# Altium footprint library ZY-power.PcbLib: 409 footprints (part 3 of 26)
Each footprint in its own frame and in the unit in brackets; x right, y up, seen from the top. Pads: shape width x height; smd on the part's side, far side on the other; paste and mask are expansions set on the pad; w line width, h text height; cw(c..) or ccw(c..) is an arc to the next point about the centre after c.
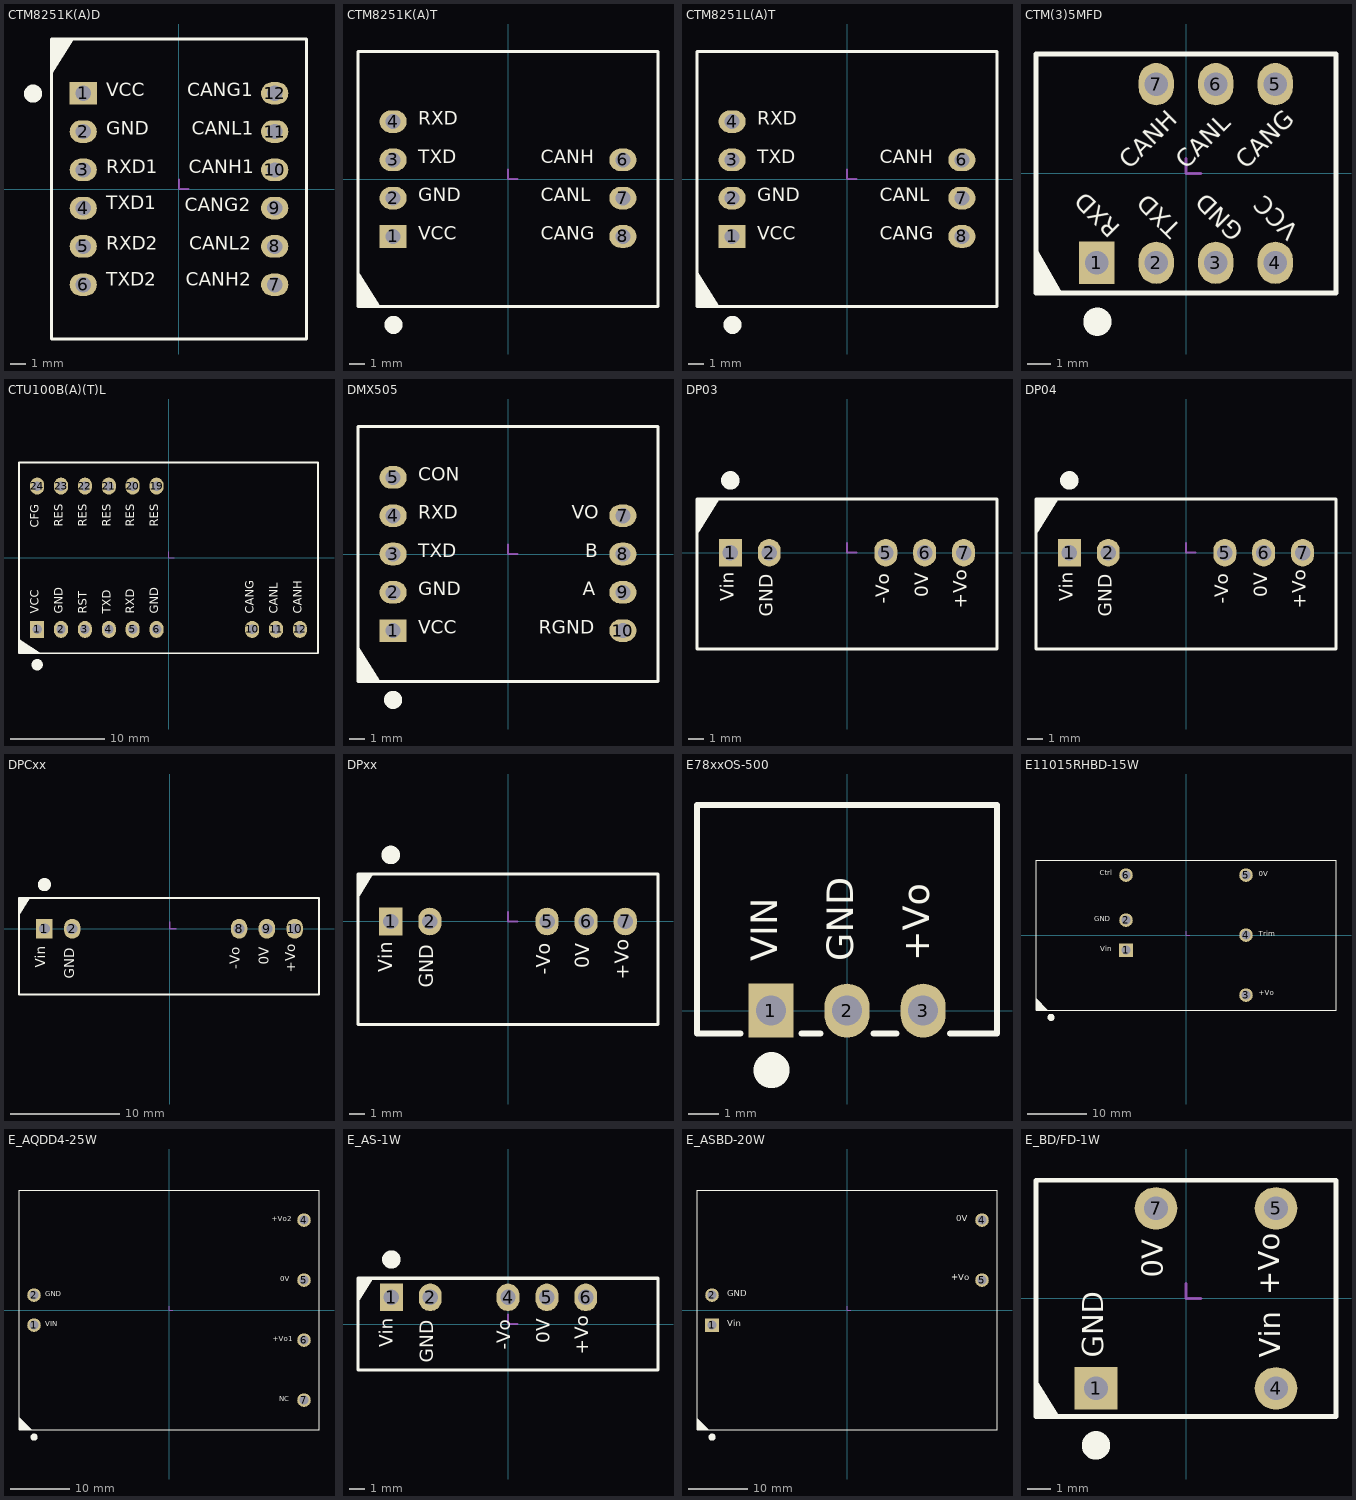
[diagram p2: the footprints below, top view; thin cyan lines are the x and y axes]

## CTM8251K(A)D [mm]
height 7.1
pads (12):
  rect 1.8x1.5 hole 1: 1(-6.35,6.35)
  oval 1.8x1.5 hole 1: 2(-6.35,3.81) 3(-6.35,1.27) 4(-6.35,-1.27) 5(-6.35,-3.81) 6(-6.35,-6.35) 7(6.35,-6.35) 8(6.35,-3.81) 9(6.35,-1.27) 10(6.35,1.27) 11(6.35,3.81) 12(6.35,6.35)
Top Overlay:
  circle w1: c-9.675,6.323 r0.1
  region: -8.45,7.62 -8.45,9.95 -6.99,9.95
  lines w0.2: -8.45,-9.95 -8.45,9.95 8.45,9.95 8.45,-9.95 -8.45,-9.95
  text "RXD2" at -4.827,-4.318 h1.52
  text "TXD2" at -4.827,-6.731 h1.52
  text "CANH2" at 0.457,-6.731 h1.52
  text "CANL2" at 0.683,-4.318 h1.52
  text "TXD1" at -4.827,-1.651 h1.52
  text "RXD1" at -4.827,0.762 h1.52
  text "GND" at -4.827,3.302 h1.52
  text "VCC" at -4.826,5.842 h1.52
  text "CANL1" at 0.861,3.302 h1.52
  text "CANH1" at 0.635,0.762 h1.52
  text "CANG2" at 0.381,-1.778 h1.52
  text "CANG1" at 0.559,5.842 h1.52
Mechanical 15:
  lines w0.127: 0,0.635 0,0 0.635,0
3D body "zhen01.stp": height 6.09, standoff -4.41, extent 6.1,6.1 6.6,6.6
3D body "zhen01.stp": height 6.09, standoff -4.41, extent 6.1,3.56 6.6,4.06
3D body "zhen01.stp": height 6.09, standoff -4.41, extent 6.1,1.02 6.6,1.52
3D body "zhen01.stp": height 6.09, standoff -4.41, extent 6.1,-1.52 6.6,-1.02
3D body "zhen01.stp": height 6.09, standoff -4.41, extent 6.1,-4.06 6.6,-3.56
3D body "zhen01.stp": height 6.09, standoff -4.41, extent 6.1,-6.6 6.6,-6.1
3D body "zhen01.stp": height 6.09, standoff -4.41, extent -6.6,-6.6 -6.1,-6.1
3D body "zhen01.stp": height 6.09, standoff -4.41, extent -6.6,-4.06 -6.1,-3.56
3D body "zhen01.stp": height 6.09, standoff -4.41, extent -6.6,-1.52 -6.1,-1.02
3D body "zhen01.stp": height 6.09, standoff -4.41, extent -6.6,1.02 -6.1,1.52
3D body "zhen01.stp": height 6.09, standoff -4.41, extent -6.6,3.56 -6.1,4.06
3D body "zhen01.stp": height 6.09, standoff -4.41, extent -6.6,6.1 -6.1,6.6
3D body: height 7.1, standoff 0, extent -8.45,-9.95 8.45,9.95

## CTM8251K(A)T [mm]
height 7.1
pads (7):
  rect 1.8x1.5 hole 1: 1(-7.62,-3.81)
  oval 1.8x1.5 hole 1: 2(-7.62,-1.27) 3(-7.62,1.27) 4(-7.62,3.81) 6(7.62,1.27) 7(7.62,-1.27) 8(7.62,-3.81)
Top Overlay:
  circle w1: c-7.593,-9.675 r0.1
  region: -9.95,-6.223 -9.95,-8.45 -8.49,-8.45 -9.838,-6.298
  lines w0.2: -9.95,-8.45 9.95,-8.45 9.95,8.45 -9.95,8.45 -9.95,-8.45
  text "VCC" at -5.938,-4.318 h1.52
  text "RXD" at -5.969,3.302 h1.52
  text "TXD" at -5.939,0.762 h1.52
  text "GND" at -5.939,-1.778 h1.52
  text "CANH" at 2.189,0.762 h1.52
  text "CANL" at 2.189,-1.778 h1.52
  text "CANG" at 2.189,-4.318 h1.52
Mechanical 15:
  lines w0.127: 0,0.635 0,0 0.635,0
3D body "zhen01.stp": height 6.09, standoff -4.41, extent 7.37,1.02 7.87,1.52
3D body "zhen01.stp": height 6.09, standoff -4.41, extent 7.37,-1.52 7.87,-1.02
3D body "zhen01.stp": height 6.09, standoff -4.41, extent 7.37,-4.06 7.87,-3.56
3D body "zhen01.stp": height 6.09, standoff -4.41, extent -7.87,-4.06 -7.37,-3.56
3D body "zhen01.stp": height 6.09, standoff -4.41, extent -7.87,-1.52 -7.37,-1.02
3D body "zhen01.stp": height 6.09, standoff -4.41, extent -7.87,1.02 -7.37,1.52
3D body "zhen01.stp": height 6.09, standoff -4.41, extent -7.87,3.56 -7.37,4.06
3D body: height 7.1, standoff 0, extent -9.95,-8.45 9.95,8.45

## CTM8251L(A)T [mm]
height 7.1
pads (7):
  rect 1.8x1.5 hole 1: 1(-7.62,-3.81)
  oval 1.8x1.5 hole 1: 2(-7.62,-1.27) 3(-7.62,1.27) 4(-7.62,3.81) 6(7.62,1.27) 7(7.62,-1.27) 8(7.62,-3.81)
Top Overlay:
  circle w1: c-7.593,-9.675 r0.1
  region: -9.95,-6.12 -9.95,-8.45 -8.49,-8.45
  lines w0.2: -9.95,-8.45 9.95,-8.45 9.95,8.45 -9.95,8.45 -9.95,-8.45
  text "CANG" at 2.189,-4.318 h1.52
  text "CANL" at 2.189,-1.778 h1.52
  text "CANH" at 2.189,0.762 h1.52
  text "GND" at -5.939,-1.778 h1.52
  text "TXD" at -5.939,0.762 h1.52
  text "RXD" at -5.969,3.302 h1.52
  text "VCC" at -5.938,-4.318 h1.52
Mechanical 15:
  lines w0.127: 0,0.635 0,0 0.635,0

## CTM(3)5MFD [mm]
height 7.7
pads (7):
  rect 1.5x1.8 hole 1: 1(-3.81,-3.81)
  oval 1.5x1.8 hole 1: 2(-1.27,-3.81) 3(1.27,-3.81) 4(3.81,-3.81) 5(3.81,3.81) 6(1.27,3.81) 7(-1.27,3.81)
Top Overlay:
  circle w1: c-3.783,-6.325 r0.1
  region: -5.284,-5.1 -6.4,-3.161 -6.4,-5.1
  lines w0.2: -6.4,-5.1 -6.4,5.1 6.4,5.1 6.4,-5.1 -6.4,-5.1
  text "CANG" at 2.748,-0.025 h1.27
  text "CANL" at 0.178,-0.025 h1.27
  text "CANH" at -2.235,-0.025 h1.27
  text "VCC" at 5.055,-2.214 h1.27
  text "GND" at 2.692,-2.252 h1.27
  text "TXD" at 0.025,-2.113 h1.27
  text "RXD" at -2.565,-2.108 h1.27
Mechanical 15:
  lines w0.127: 0,0.635 0,0 0.635,0

## CTU100B(A)(T)L [mm]
height 6.5
pads (15):
  rect 1.5x1.8 hole 1: 1(-13.97,-7.62)
  oval 1.5x1.8 hole 1: 2(-11.43,-7.62) 3(-8.89,-7.62) 4(-6.35,-7.62) 5(-3.81,-7.62) 6(-1.27,-7.62) 10(8.89,-7.62) 11(11.43,-7.62) 12(13.97,-7.62) 19(-1.27,7.62) 20(-3.81,7.62) 21(-6.35,7.62) 22(-8.89,7.62) 23(-11.43,7.62) 24(-13.97,7.62)
Top Overlay:
  circle w1: c-13.97,-11.375 r0.1
  region: -13.57,-10.15 -15.9,-10.15 -15.9,-8.69
  lines w0.2: -15.9,-10.15 15.9,-10.15 15.9,10.15 -15.9,10.15 -15.9,-10.15
  text "RES" at -0.762,3.29 h1.52
  text "RES" at -3.302,3.29 h1.52
  text "RES" at -5.842,3.29 h1.52
  text "RES" at -8.382,3.29 h1.52
  text "RES" at -10.922,3.29 h1.52
  text "CFG" at -13.462,3.192 h1.52
  text "CANH" at 14.478,-5.969 h1.52
  text "CANL" at 11.938,-5.969 h1.52
  text "CANG" at 9.398,-5.969 h1.52
  text "GND" at -0.762,-5.969 h1.52
  text "RXD" at -3.302,-5.969 h1.52
  text "TXD" at -5.842,-5.969 h1.52
  text "RST" at -8.382,-5.969 h1.52
  text "GND" at -10.922,-5.969 h1.52
  text "VCC" at -13.462,-5.969 h1.52
Mechanical 15:
  lines w0.127: 0,0.635 0,0 0.635,0

## DMX505 [mm]
height 7.1
pads (9):
  rect 1.8x1.5 hole 1: 1(-7.62,-5.08)
  oval 1.8x1.5 hole 1: 2(-7.62,-2.54) 3(-7.62,0) 4(-7.62,2.54) 5(-7.62,5.08) 7(7.62,2.54) 8(7.62,0) 9(7.62,-2.54) 10(7.62,-5.08)
Top Overlay:
  circle w1: c-7.62,-9.675 r0.1
  region: -9.95,-6.12 -9.95,-8.45 -8.49,-8.45
  lines w0.2: -9.95,-8.45 9.95,-8.45 9.95,8.45 -9.95,8.45 -9.95,-8.45
  text "VO" at 4.215,2.032 h1.52
  text "A" at 4.952,-3.048 h1.52
  text "B" at 5.126,-0.508 h1.52
  text "RGND" at 2.032,-5.588 h1.52
  text "CON" at -5.939,4.572 h1.52
  text "RXD" at -5.939,2.032 h1.52
  text "TXD" at -5.939,-0.508 h1.52
  text "VCC" at -5.938,-5.588 h1.52
  text "GND" at -5.939,-3.048 h1.52
Mechanical 15:
  lines w0.127: 0,0.635 0,0 0.635,0
3D body "zhen01.stp": height 6.09, standoff -4.41, extent -7.87,4.83 -7.37,5.33
3D body "zhen01.stp": height 6.09, standoff -4.41, extent -7.87,2.29 -7.37,2.79
3D body "zhen01.stp": height 6.09, standoff -4.41, extent -7.87,-0.25 -7.37,0.25
3D body "zhen01.stp": height 6.09, standoff -4.41, extent -7.87,-2.79 -7.37,-2.29
3D body "zhen01.stp": height 6.09, standoff -4.41, extent -7.87,-5.33 -7.37,-4.83
3D body "zhen01.stp": height 6.09, standoff -4.41, extent 7.37,-0.25 7.87,0.25
3D body "zhen01.stp": height 6.09, standoff -4.41, extent 7.37,-2.79 7.87,-2.29
3D body "zhen01.stp": height 6.09, standoff -4.41, extent 7.37,-5.33 7.87,-4.83
3D body: height 7.1, standoff 0, extent -9.95,-8.45 9.95,8.45
3D body "zhen01.stp": height 6.09, standoff -4.41, extent 7.37,2.29 7.87,2.79

## DP03 [mm]
height 12.5
pads (5):
  rect 1.5x1.8 hole 1: 1(-7.62,0)
  oval 1.5x1.8 hole 1: 2(-5.08,0) 5(2.533,0) 6(5.073,0) 7(7.62,0)
Top Overlay:
  circle w1: c-7.62,4.725 r0.1
  region: -9.8,1.17 -9.8,3.5 -8.34,3.5
  lines w0.2: -9.8,-6.3 9.8,-6.3 9.8,3.5 -9.8,3.5 -9.8,-6.3
  text "0V" at 5.588,-2.909 h1.52
  text "+Vo" at 8.128,-3.649 h1.52
  text "-Vo" at 3.048,-3.337 h1.52
  text "GND" at -4.572,-4.191 h1.52
  text "Vin" at -7.112,-3.181 h1.52
Mechanical 15:
  lines w0.127: 0,0.635 0,0 0.635,0

## DP04 [mm]
height 12.5
pads (5):
  rect 1.5x1.8 hole 1: 1(-7.62,0)
  oval 1.5x1.8 hole 1: 2(-5.08,0) 5(2.533,0) 6(5.073,0) 7(7.62,0)
Top Overlay:
  circle w1: c-7.62,4.725 r0.1
  region: -9.8,1.17 -9.8,3.5 -8.34,3.5
  lines w0.2: -9.8,-6.3 -9.8,3.5 9.8,3.5 9.8,-6.3 -9.8,-6.3
  text "Vin" at -7.112,-3.181 h1.52
  text "GND" at -4.572,-4.191 h1.52
  text "-Vo" at 3.048,-3.337 h1.52
  text "+Vo" at 8.128,-3.649 h1.52
  text "0V" at 5.588,-2.909 h1.52
Mechanical 15:
  lines w0.127: 0,0.635 0,0 0.635,0

## DPCxx [mm]
height 11.4
pads (5):
  rect 1.5x1.8 hole 1: 1(-11.43,0)
  oval 1.5x1.8 hole 1: 2(-8.89,0) 8(6.35,0) 9(8.89,0) 10(11.43,0)
Top Overlay:
  circle w1: c-11.43,4.025 r0.1
  region: -13.75,1.214 -13.75,2.8 -12.756,2.8
  lines w0.2: -13.75,-6 -13.75,2.8 13.65,2.8 13.65,-6 -13.75,-6
  text "Vin" at -11.049,-3.562 h1.52
  text "GND" at -8.382,-4.572 h1.52
  text "0V" at 9.398,-3.29 h1.52
  text "-Vo" at 6.731,-3.718 h1.52
  text "+Vo" at 11.811,-4.03 h1.52
Mechanical 15:
  lines w0.127: 0,0.635 0,0 0.635,0
3D body "zhenjao01.stp": height 8.36, standoff -4.08, extent -12.13,-1.48 -10.73,0.12
3D body: height 11.4, standoff 0, extent -13.75,-6 13.65,2.8
3D body "zhenjao01.stp": height 8.36, standoff -4.08, extent -9.59,-1.48 -8.19,0.12
3D body "zhenjao01.stp": height 8.36, standoff -4.08, extent 5.65,-1.48 7.05,0.12
3D body "zhenjao01.stp": height 8.36, standoff -4.08, extent 8.19,-1.48 9.59,0.12
3D body "zhenjao01.stp": height 8.36, standoff -4.08, extent 10.73,-1.48 12.13,0.12

## DPxx [mm]
height 12.5
pads (5):
  rect 1.5x1.8 hole 1: 1(-7.62,0)
  oval 1.5x1.8 hole 1: 2(-5.08,0) 5(2.54,0) 6(5.08,0) 7(7.62,0)
Top Overlay:
  circle w1: c-7.62,4.325 r0.1
  region: -9.75,1.514 -9.75,3.1 -8.756,3.1
  lines w0.2: -9.75,-6.7 9.75,-6.7 9.75,3.1 -9.75,3.1 -9.75,-6.7
  text "Vin" at -7.239,-3.307 h1.52
  text "GND" at -4.572,-4.321 h1.52
  text "-Vo" at 3.048,-3.465 h1.52
  text "0V" at 5.568,-3.037 h1.52
  text "+Vo" at 8.128,-3.775 h1.52
Mechanical 15:
  lines w0.127: 0,0.635 0,0 0.635,0
3D body "zhenjao01.stp": height 8.36, standoff -4.08, extent 6.92,-1.48 8.32,0.12
3D body "zhenjao01.stp": height 8.36, standoff -4.08, extent 4.38,-1.48 5.78,0.12
3D body "zhenjao01.stp": height 8.36, standoff -4.08, extent 1.84,-1.48 3.24,0.12
3D body "zhenjao01.stp": height 8.36, standoff -4.08, extent -5.78,-1.48 -4.38,0.12
3D body "zhenjao01.stp": height 8.36, standoff -4.08, extent -8.32,-1.48 -6.92,0.12
3D body: height 12.5, standoff 0, extent -9.75,-6.7 9.75,3.1

## E78xxOS-500 [mm]
height 11
pads (3):
  rect 1.5x1.8 hole 1: 1(-2.54,0)
  oval 1.5x1.8 hole 1: 2(0,0) 3(2.54,0)
Top Overlay:
  circle w1: c-2.513,-1.987 r0.1
  lines w0.2: -3.556,-0.762 -5,-0.762 -5,6.858 5,6.858 5,-0.762 3.429,-0.762 ; -1.524,-0.762 -0.889,-0.762 ; 0.889,-0.762 1.651,-0.762
  text "+Vo" at 3.048,1.651 h1.52
  text "GND" at 0.508,1.651 h1.52
  text "VIN" at -2.032,1.651 h1.52
Mechanical 15:
  lines w0.127: 0,0.635 0,0 0.635,0

## E11015RHBD-15W [mm]
height 12.7
pads (6):
  rect 2.3x2.3 hole 1.5: 1(-10.16,-2.54)
  round 2.3 hole 1.5: 2(-10.16,2.54) 3(10.16,-10.16) 4(10.16,0) 5(10.16,10.16) 6(-10.16,10.16)
Top Overlay:
  circle w1: c-22.86,-13.925 r0.1
  region: -25.4,-12.7 -23.425,-12.7 -25.4,-10.725
  lines w0.2: -25.4,-12.7 25.4,-12.7 25.4,12.7 -25.4,12.7 -25.4,-12.7
  text "Ctrl" at -14.57,9.779 h1.52
  text "Trim" at 12.319,-0.508 h1.52
  text "Vin" at -14.485,-3.048 h1.52
  text "GND" at -15.495,2.032 h1.52
  text "0V" at 12.319,9.652 h1.52
  text "+Vo" at 12.319,-10.541 h1.52
Mechanical 15:
  lines w0.127: 0,0.635 0,0 0.635,0

## E_AQDD4-25W [mm]
height 13.8
pads (6):
  round 2.3 hole 1.5: 1(-22.86,-2.54) 2(-22.86,2.54) 4(22.86,15.24) 5(22.86,5.08) 6(22.86,-5.08) 7(22.86,-15.24)
Top Overlay:
  circle w1: c-22.86,-21.525 r0.1
  region: -25.298,-20.203 -23.323,-20.203 -25.298,-18.228
  lines w0.2: -25.4,-20.3 -25.4,20.3 0,20.3 25.4,20.3 25.4,-20.3 -25.4,-20.3
  text "VIN" at -20.955,-3.048 h1.52
  text "GND" at -20.955,2.032 h1.52
  text "0V" at 18.876,4.572 h1.52
  text "+Vo2" at 17.399,14.732 h1.52
  text "+Vo1" at 17.577,-5.588 h1.52
  text "NC" at 18.665,-15.748 h1.52
Mechanical 15:
  lines w0.127: 0,0.635 0,0 0.635,0

## E_AS-1W [mm]
height 10.1
pads (5):
  rect 1.5x1.8 hole 1: 1(-7.62,1.75)
  oval 1.5x1.8 hole 1: 2(-5.08,1.75) 4(0,1.75) 5(2.54,1.75) 6(5.08,1.75)
Top Overlay:
  circle w1: c-7.62,4.225 r0.1
  region: -9.8,1.414 -9.8,3 -8.806,3
  lines w0.2: -9.8,-3 -9.8,3 9.8,3 9.8,-3 -9.8,-3
  text "Vin" at -7.225,-1.521 h1.52
  text "GND" at -4.575,-2.531 h1.52
  text "-Vo" at 0.45,-1.677 h1.52
  text "0V" at 3.013,-1.249 h1.52
  text "+Vo" at 5.55,-1.989 h1.52
Mechanical 15:
  lines w0.127: 0,0.635 0,0 0.635,0

## E_ASBD-20W [mm]
height 13.8
pads (4):
  rect 2.3x2.3 hole 1.5: 1(-22.86,-2.54)
  round 2.3 hole 1.5: 2(-22.86,2.54) 4(22.86,15.24) 5(22.86,5.08)
Top Overlay:
  circle w1: c-22.86,-21.525 r0.1
  region: -25.4,-20.3 -23.425,-20.3 -25.4,-18.325
  lines w0.2: -25.4,-20.3 -25.4,20.3 25.4,20.3 25.4,-20.3 -25.4,-20.3
  text "GND" at -20.32,2.034 h1.78
  text "Vin" at -20.32,-3.046 h1.78
  text "+Vo" at 17.653,4.699 h1.78
  text "0V" at 18.517,14.732 h1.78
Mechanical 15:
  lines w0.127: 0,0.635 0,0 0.635,0

## E_BD/FD-1W [mm]
height 7.7
pads (4):
  rect 1.8x1.8 hole 1: 1(-3.81,-3.81)
  round 1.8 hole 1: 4(3.81,-3.81) 5(3.81,3.81) 7(-1.27,3.81)
Top Overlay:
  circle w1: c-3.81,-6.225 r0.1
  region: -6.35,-3.414 -6.35,-5 -5.356,-5
  lines w0.2: -6.35,-5 6.35,-5 6.35,5 -6.35,5 -6.35,-5
  text "GND" at -3.2,-2.516 h1.52
  text "Vin" at 4.293,-2.515 h1.52
  text "+Vo" at 4.244,0.124 h1.52
  text "0V" at -0.686,0.864 h1.52
Mechanical 15:
  lines w0.127: 0,0.635 0,0 0.635,0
